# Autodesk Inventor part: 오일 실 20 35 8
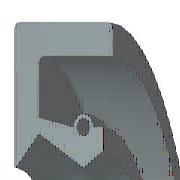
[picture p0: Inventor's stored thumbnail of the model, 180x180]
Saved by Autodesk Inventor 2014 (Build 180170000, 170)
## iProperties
Created: 2012-02
Part Number: 오일 실 20 35 8
Material: 고무
Description: 오일-실
Document SubType Name: Modeling
Standard: KS B 2804
Designer: mduedu
Standards Organization: KS
Language: ko-KR
Size Designation: D - 20 35 8
Categories: <MemberInstance><Categories><Category DisplayName="샤프트 부품" InternalName="7f7aeb1f-a693-4053-b835-cee3144e0d98" Mnemonic="SHFT"><Category DisplayName="실링" Intern
Density: 0.93 g/cm^3
Appearance: 고무 - 검은색 - 버전 1.1
Mass: 2.54606 g
Surface Area: 35.9421 cm^2
Volume: 2.7377 cm^3
IsCustomPart: 1
Author: mduedu
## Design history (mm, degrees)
revolve "본체" stored, may be unused: angle "d17" = 90 deg
revolve "스프링1" stored, may be unused: angle "d18" = 90 deg
body "Solid1"
sketch "스케치1"
  geometry: L1 (0, 17.5)-(8, 17.5); L2 (8, 15.75)-(1.75, 15.75); L3 (1.75, 11.75)-(4.9, 10); L4 (4.9, 10)-(0, 10); L5 (0, 0)-(9.586, 0) reference; L6 (4.9, 10)-(6.3, 10.875); L7 (0, 18)-(0, -3) reference; L8 (-1.941, 0)-(11.507, 0) reference; L9 (4.2, 12.1)-(1.75, 12.71); L10 (1.75, 12.71)-(1.75, 15.75); L11 (0, 17.5)-(0, 10.088); L12 (4.9, 10)-(0, 10); L13 (1.75, 11.75)-(0.152, 10.028); L14 (8, 17.5)-(8, 15.75); L15 (5.6, 12.1)-(6.3, 12.1); L16 (6.3, 12.1)-(6.3, 10.875); C1 r 0.455 at (4.9, 12.1); A1 r 0.7 centre (4.9, 12.1) between (5.6, 12.1) and (4.2, 12.1); A2 r 0.088 centre (0.088, 10.088) between (0, 10.088) and (0.152, 10.028); 1 further point
  constraints: 28 end point, 5 horizontal alignment, 5 point on line, 4 point on circle, 4 vertical alignment, 3 centre point, 3 tangent, 2 collinear, 2 horizontal, 2 perpendicular, 1 coincident, 1 parallel
  dimensions: "d0" = 35 diameter of L1 L5 (= SD2); "d1" = 1.75 distance of L1.end L2.start (= SD); "d2" = 0.91 diameter of C1 (= SPDI); "d3" = 1.4 diameter of A1 (= SPDA); "d4" = 20 diameter of L3.end L5 (= NND); "d5" = 23.5 diameter of L3.start L5 (= TKDM); "d7" = 25.42 diameter of L9.end L5 (= TKDM + 0.24 x SWDT); "d8" = 1.75 distance between parallel lines of L11 L10 (= SD); "d9" = 4.9 distance from line of L11 C1.centre (= SPDST); "d10" = 24.2 diameter of C1.centre L5 (= HLDM); "d11" = 0.0875 radius of A2 (= 0.25 x LAB); "d12" = 6.3 distance between parallel lines of L11 L16 (= SDI); "d13" = 21.75 diameter of L6.end L5 (= ABDM); "d14" = 8 distance from line of L11 L1.end (= SWDT)
fillet "모깎기1" dims "d6" = 0.3 (= RR)
other parameters: "SD2" = 35 [user parameter; used in 1 equation term], "SWDT" = 8 [user parameter; used in 2 equation terms], "RR" = 0.3 [user parameter; used in 1 equation term], "SD" = 1.75 [user parameter; used in 2 equation terms], "NND" = 20 [user parameter; used in 1 equation term], "SPDA" = 1.4 [user parameter; used in 1 equation term], "SPDI" = 0.91 [user parameter; used in 1 equation term], "TKDM" = 23.5 [user parameter; used in 2 equation terms], "HLDM" = 24.2 [user parameter; used in 1 equation term], "ABDM" = 21.75 [user parameter; used in 1 equation term], "SDI" = 6.3 [user parameter; used in 1 equation term], "SPDST" = 4.9 [user parameter; used in 1 equation term], "LAB" = 0.35 [user parameter; used in 1 equation term], "d15" = 0, "d16" = 0, "d19" = 0
